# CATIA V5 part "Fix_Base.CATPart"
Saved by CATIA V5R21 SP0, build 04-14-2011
Part number: Fix_Base
Bounding box of the stored display mesh (mm): x -92.8 to 92.8, y -87.8 to 87.8, z 0 to 2.8
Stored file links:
  C:\Users\Pouria\Desktop\Box\Fix_Base.CATPart
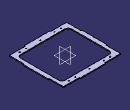
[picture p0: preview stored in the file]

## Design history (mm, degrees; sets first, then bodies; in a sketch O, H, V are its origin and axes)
Body1 (main body)
  Sketch1 on xy-plane, origin (0, 0, 0), H (1, 0, 0), V (0, 1, 0)
    line L1 (80, 70) -> (80, -70)
    line L2 (80, -70) -> (-80, -70)
    line L3 (-80, -70) -> (-80, 70)
    line L4 (-80, 70) -> (80, 70)
    line L5 (90, 85) -> (90, 40)
    line L6 (90, -85) -> (40, -85)
    line L7 (-90, -85) -> (-90, -40)
    line L8 (-90, 85) -> (-40, 85)
    line L9 (90, 40) -> (92.8, 40)
    line L10 (92.8, 40) -> (92.8, -40)
    line L11 (92.8, -40) -> (90, -40)
    point P12 (90, -40)
    point P13 (-90, 40)
    line L12 (-90, 40) -> (-92.8, 40)
    line L13 (-92.8, 40) -> (-92.8, -40)
    line L14 (-92.8, -40) -> (-90, -40)
    point P17 (40, 85)
    line L15 (40, 85) -> (40, 87.8)
    line L16 (40, 87.8) -> (-40, 87.8)
    line L17 (-40, 87.8) -> (-40, 85)
    line L18 (40, -85) -> (40, -87.8)
    line L19 (40, -87.8) -> (-40, -87.8)
    line L20 (-40, -87.8) -> (-40, -85)
    point P24 (-40, -85)
    line L21 (90, -40) -> (90, -85)
    line L22 (40, 85) -> (90, 85)
    line L23 (-90, 40) -> (-90, 85)
    line L24 (-40, -85) -> (-90, -85)
    circle A1 centre (0, 77.5) radius 1.9
    point P25 (0, 77.5)
    circle A2 centre (0, -77.5) radius 1.9
    point P26 (0, -77.5)
    circle A3 centre (65, 77.5) radius 1.9
    point P27 (65, 77.5)
    circle A4 centre (-65, 77.5) radius 1.9
    point P28 (-65, 77.5)
    circle A5 centre (-65, -77.5) radius 1.9
    point P29 (-65, -77.5)
    circle A6 centre (-45, -77.5) radius 1.5
    point P30 (-45, -77.5)
    circle A7 centre (45, -77.5) radius 1.5
    point P31 (45, -77.5)
    circle A8 centre (65, -77.5) radius 1.9
    point P32 (65, -77.5)
    circle A9 centre (45, 77.5) radius 1.5
    point P33 (45, 77.5)
    circle A10 centre (-45, 77.5) radius 1.5
    point P34 (-45, 77.5)
    distance L1 L5 = 10
    distance L2 L6 = 15
    distance L1 L3 = 160
    distance L4 L2 = 140
    length L11 = 2.8
    length L15 = 2.8
    length L10 = 80
    length L16 = 80
    distance P25 L4 = 7.5
    distance P33 L4 = 7.5
    distance P27 L4 = 7.5
    distance P34 L4 = 7.5
    distance P28 L4 = 7.5
    distance P29 L2 = 7.5
    distance P30 L2 = 7.5
    distance P26 L2 = 7.5
    distance P31 L2 = 7.5
    distance P32 L2 = 7.5
    distance P32 L21 = 25
    distance P29 L7 = 25
    distance P27 L5 = 25
    distance P28 L23 = 25
    radius A3 = 1.9
    radius A4 = 1.9
    radius A1 = 1.9
    radius A8 = 1.9
    radius A2 = 1.9
    radius A5 = 1.9
    distance P33 L5 = 45
    distance P34 L23 = 45
    distance P31 L21 = 45
    distance P30 L7 = 45
    radius A7 = 1.5
    radius A6 = 1.5
    radius A9 = 1.5
    radius A10 = 1.5
    vertical: L1 V, L3 V, L5 V, L7 V, L10 V, L13 V, L15 V, L17 V, L18 V, L20 V, L21 V, L23 V
    horizontal: L2 H, L4 H, L6 H, L8 H, L9 H, L11 H, L12 H, L14 H, L16 H, L19 H, L22 H, L24 H
    equidistance: L1 L3 O, L2 L4 O, L5 L7 O, L6 L8 O
    coincidence: P12 L5, P13 L7, P17 L8, P24 L6, L18 L15, L20 L17, L11 L14, L9 L12, L5 L21, L8 L22, L7 L23, L6 L24, P25 V, P26 V
    symmetry: L10 L13 V, L19 L16 H, L15 L17 V, L18 L20 V, L11 L9 H, L14 L12 H
  Pad1: profile Sketch1, direction (0, 0, 1), length 2.8
  Fillet1: radius 10, on edge [face of Pad1 from Sketch1.L4 | face of Pad1 from Sketch1.L3]; edge [face of Pad1 from Sketch1.L1 | face of Pad1 from Sketch1.L4]; edge [face of Pad1 from Sketch1.L2 | face of Pad1 from Sketch1.L1]; edge [face of Pad1 from Sketch1.L3 | face of Pad1 from Sketch1.L2]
